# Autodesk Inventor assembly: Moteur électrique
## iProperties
Created: 2002-05
Part Number: Moteur électrique
Document SubType Name: Assemblage
Designer: Flavien MARTY
Control State: 0
Master: False
Checked Out: False
Shininess: 41.0
Length Units: 11269
Angle Units: 11279
Time Units: 11290
Mass Units: 11283
Length Display Precision: 3
Angle Display Precision: 2
Density: 0.0
Volumn: 0.0
Area: 0.0
PropertySet Name: Model Information
Author: Flavien MARTY
